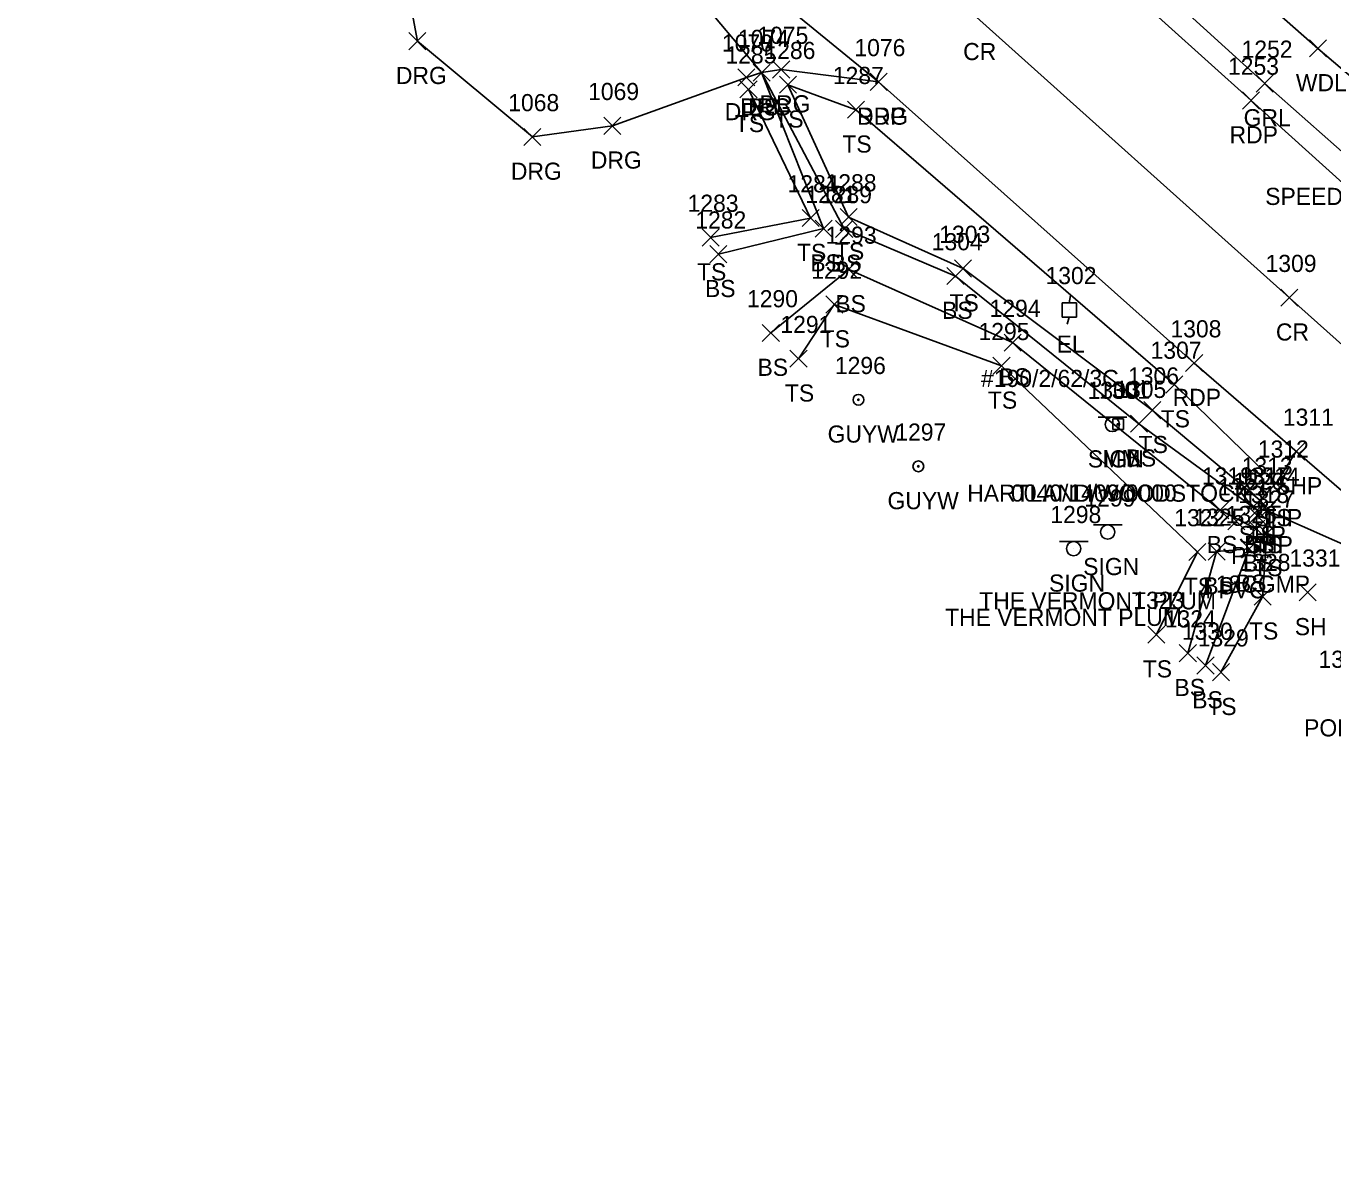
# Model space of a CAD drawing. Extents: x 1647133 to 1649138, y 411736 to 414924.
# Drawn here: x 1648782.9 to 1648935.4, y 411750.9 to 411884.6 of the extents above; entities that cross this region are included whole.
import ezdxf

# ---------------------------------------------------------------- set-up
doc = ezdxf.new("R2010")
doc.units = 0
for name, color, linetype in [('D_A', 7, 'Continuous'), ('D_C', 7, 'Continuous'), ('D_I', 7, 'Continuous'), ('D_TIC', 7, 'Continuous'), ('L_A', 7, 'Continuous'), ('L_I', 7, 'Continuous'), ('L_TIC', 7, 'Continuous'), ('LAWA', 7, 'Continuous'), ('LELB', 7, 'Continuous'), ('P_A', 7, 'Continuous'), ('P_I', 7, 'Continuous'), ('P_TIC', 7, 'Continuous'), ('PET', 7, 'Continuous'), ('PRC', 7, 'Continuous'), ('PSP', 7, 'Continuous'), ('R_A', 7, 'Continuous'), ('R_I', 7, 'Continuous'), ('R_TIC', 7, 'Continuous'), ('RDG', 7, 'Continuous'), ('RGR', 7, 'Continuous'), ('S_A', 7, 'Continuous'), ('S_C', 7, 'Continuous'), ('S_I', 7, 'Continuous'), ('SRM', 7, 'Continuous'), ('SSGN', 7, 'Continuous'), ('U_A', 7, 'Continuous'), ('U_C', 7, 'Continuous'), ('U_I', 7, 'Continuous'), ('UEPT', 7, 'Continuous'), ('UPGW', 7, 'Continuous')]:
    doc.layers.add(name, color=color, linetype=linetype)

msp = doc.modelspace()

# ---------------------------------------------------------------- linework, layer by layer
at = {"layer": 'D_TIC'}
for points in [[(1648923.17, 411825.82), (1648925.17, 411827.82)], [(1648925.17, 411825.82), (1648923.17, 411827.82)], [(1648925.57, 411826.48), (1648927.57, 411828.48)], [(1648927.57, 411826.48), (1648925.57, 411828.48)]]:
    msp.add_lwpolyline(points, dxfattribs=at)
at = {"layer": 'L_TIC'}
for points in [[(1648932.69, 411880.99), (1648934.69, 411882.99)], [(1648934.69, 411880.99), (1648932.69, 411882.99)], [(1648867.76, 411878.16), (1648869.76, 411880.16)], [(1648869.76, 411878.16), (1648867.76, 411880.16)], [(1648867.76, 411878.16), (1648869.76, 411880.16)], [(1648869.76, 411878.16), (1648867.76, 411880.16)], [(1648866.23, 411876.22), (1648868.23, 411878.22)], [(1648868.23, 411876.22), (1648866.23, 411878.22)], [(1648870.83, 411876.75), (1648872.83, 411878.75)], [(1648872.83, 411876.75), (1648870.83, 411878.75)], [(1648870.83, 411876.75), (1648872.83, 411878.75)], [(1648872.83, 411876.75), (1648870.83, 411878.75)], [(1648878.77, 411873.83), (1648880.77, 411875.83)], [(1648880.77, 411873.83), (1648878.77, 411875.83)], [(1648873.48, 411861.19), (1648875.48, 411863.19)], [(1648875.48, 411861.19), (1648873.48, 411863.19)], [(1648877.91, 411861.31), (1648879.91, 411863.31)], [(1648879.91, 411861.31), (1648877.91, 411863.31)], [(1648861.81, 411858.92), (1648863.81, 411860.92)], [(1648863.81, 411858.92), (1648861.81, 411860.92)], [(1648875, 411859.96), (1648877, 411861.96)], [(1648877, 411859.96), (1648875, 411861.96)], [(1648877.39, 411859.92), (1648879.39, 411861.92)], [(1648879.39, 411859.92), (1648877.39, 411861.92)], [(1648862.71, 411856.97), (1648864.71, 411858.97)], [(1648864.71, 411856.97), (1648862.71, 411858.97)], [(1648877.92, 411855.2), (1648879.92, 411857.2)], [(1648879.92, 411855.2), (1648877.92, 411857.2)], [(1648890.38, 411854.43), (1648892.38, 411856.43)], [(1648892.38, 411854.43), (1648890.38, 411856.43)], [(1648891.27, 411855.3), (1648893.27, 411857.3)], [(1648893.27, 411855.3), (1648891.27, 411857.3)], [(1648876.24, 411851.1), (1648878.24, 411853.1)], [(1648878.24, 411851.1), (1648876.24, 411853.1)], [(1648868.83, 411847.78), (1648870.83, 411849.78)], [(1648870.83, 411847.78), (1648868.83, 411849.78)], [(1648897.05, 411846.66), (1648899.05, 411848.66)], [(1648899.05, 411846.66), (1648897.05, 411848.66)], [(1648872.07, 411844.78), (1648874.07, 411846.78)], [(1648874.07, 411844.78), (1648872.07, 411846.78)], [(1648895.76, 411843.95), (1648897.76, 411845.95)], [(1648897.76, 411843.95), (1648895.76, 411845.95)], [(1648915.93, 411841.77), (1648917.93, 411843.77)], [(1648917.93, 411841.77), (1648915.93, 411843.77)], [(1648913.35, 411838.77), (1648915.35, 411840.77)], [(1648915.35, 411838.77), (1648913.35, 411840.77)], [(1648911.8, 411837.2), (1648913.8, 411839.2)], [(1648913.8, 411837.2), (1648911.8, 411839.2)], [(1648927.8, 411830.24), (1648929.8, 411832.24)], [(1648929.8, 411830.24), (1648927.8, 411832.24)], [(1648925.91, 411828.26), (1648927.91, 411830.26)], [(1648927.91, 411828.26), (1648925.91, 411830.26)], [(1648921.27, 411827.1), (1648923.27, 411829.1)], [(1648923.27, 411827.1), (1648921.27, 411829.1)], [(1648921.27, 411827.1), (1648923.27, 411829.1)], [(1648923.27, 411827.1), (1648921.27, 411829.1)], [(1648925.61, 411827.1), (1648927.61, 411829.1)], [(1648927.61, 411827.1), (1648925.61, 411829.1)], [(1648926.73, 411827.08), (1648928.73, 411829.08)], [(1648928.73, 411827.08), (1648926.73, 411829.08)], [(1648925.49, 411824.94), (1648927.49, 411826.94)], [(1648927.49, 411824.94), (1648925.49, 411826.94)], [(1648926.72, 411824.41), (1648928.72, 411826.41)], [(1648928.72, 411824.41), (1648926.72, 411826.41)], [(1648918.61, 411822.23), (1648920.61, 411824.23)], [(1648920.61, 411822.23), (1648918.61, 411824.23)], [(1648920.86, 411822.28), (1648922.86, 411824.28)], [(1648922.86, 411822.28), (1648920.86, 411824.28)], [(1648924.67, 411822.59), (1648926.67, 411824.59)], [(1648926.67, 411822.59), (1648924.67, 411824.59)], [(1648931.49, 411817.52), (1648933.49, 411819.52)], [(1648933.49, 411817.52), (1648931.49, 411819.52)], [(1648926.23, 411817.01), (1648928.23, 411819.01)], [(1648928.23, 411817.01), (1648926.23, 411819.01)], [(1648913.83, 411812.59), (1648915.83, 411814.59)], [(1648915.83, 411812.59), (1648913.83, 411814.59)], [(1648917.5, 411810.42), (1648919.5, 411812.42)], [(1648919.5, 411810.42), (1648917.5, 411812.42)], [(1648919.57, 411808.98), (1648921.57, 411810.98)], [(1648921.57, 411808.98), (1648919.57, 411810.98)], [(1648921.36, 411808.2), (1648923.36, 411810.2)], [(1648923.36, 411808.2), (1648921.36, 411810.2)]]:
    msp.add_lwpolyline(points, dxfattribs=at)
at = {"layer": 'LAWA'}
msp.add_lwpolyline([(1648868.17, 411960.17), (1648864.04, 411954.98), (1648884.1, 411929.27), (1648898.93, 411912.58), (1648933.69, 411881.99), (1648961.81, 411858.05), (1648999.6, 411820.73), (1649038.84, 411784.04)], dxfattribs=at)
at = {"layer": 'LELB'}
for points in [[(1648751.1, 411983.83), (1648760.09, 411978.22), (1648771.97, 411970.92), (1648795.55, 411950.44), (1648830.26, 411918.42), (1648852.65, 411898.35), (1648868.76, 411879.16), (1648878.39, 411860.92), (1648891.38, 411855.43), (1648912.8, 411838.2), (1648926.61, 411828.1), (1648926.49, 411825.94), (1648922.27, 411828.1)], [(1648868.76, 411879.16), (1648876, 411860.96), (1648863.71, 411857.97)], [(1648871.83, 411877.75), (1648879.77, 411874.83), (1648916.93, 411842.77), (1648928.8, 411831.24)], [(1648871.83, 411877.75), (1648878.91, 411862.31), (1648892.27, 411856.3), (1648914.35, 411839.77), (1648926.91, 411829.26)], [(1648862.81, 411859.92), (1648874.48, 411862.19), (1648867.23, 411877.22)], [(1648869.83, 411848.78), (1648878.92, 411856.2), (1648898.05, 411847.66), (1648922.27, 411828.1)], [(1648873.07, 411845.78), (1648877.24, 411852.1), (1648896.76, 411844.95), (1648919.61, 411823.23), (1648914.83, 411813.59)], [(1648927.73, 411828.08), (1648927.72, 411825.41), (1648927.23, 411818.01), (1648922.36, 411809.2)], [(1648918.5, 411811.42), (1648921.86, 411823.28), (1648925.67, 411823.59), (1648920.57, 411809.98)]]:
    msp.add_lwpolyline(points, dxfattribs=at)
at = {"layer": 'P_TIC'}
for points in [[(1648881.41, 411877.08), (1648883.41, 411879.08)], [(1648883.41, 411877.08), (1648881.41, 411879.08)], [(1648924.88, 411874.91), (1648926.88, 411876.91)], [(1648926.88, 411874.91), (1648924.88, 411876.91)], [(1648929.35, 411851.9), (1648931.35, 411853.9)], [(1648931.35, 411851.9), (1648929.35, 411853.9)], [(1648918.24, 411844.27), (1648920.24, 411846.27)], [(1648920.24, 411844.27), (1648918.24, 411846.27)], [(1648930.15, 411833.96), (1648932.15, 411835.96)], [(1648932.15, 411833.96), (1648930.15, 411835.96)], [(1648927.8, 411830.24), (1648929.8, 411832.24)], [(1648929.8, 411830.24), (1648927.8, 411832.24)], [(1648925.91, 411828.26), (1648927.91, 411830.26)], [(1648927.91, 411828.26), (1648925.91, 411830.26)], [(1648926.73, 411827.08), (1648928.73, 411829.08)], [(1648928.73, 411827.08), (1648926.73, 411829.08)]]:
    msp.add_lwpolyline(points, dxfattribs=at)
at = {"layer": 'PET'}
for points in [[(1648755.32, 411988.12), (1648772.85, 411971.96), (1648796.64, 411951.34), (1648831.69, 411920.96), (1648865.67, 411891.79), (1648882.41, 411878.08), (1648919.24, 411845.27), (1648942.74, 411824.95), (1648978.24, 411792.71), (1649017.21, 411756.44)], [(1648794.52, 411987.62), (1648826.41, 411959.79), (1648844.85, 411943.99), (1648873.22, 411921.13), (1648895.79, 411903), (1648925.88, 411875.91), (1648954.39, 411850.18), (1648992.64, 411815.07), (1649033.55, 411777.71)]]:
    msp.add_lwpolyline(points, dxfattribs=at)
at = {"layer": 'PRC'}
msp.add_lwpolyline([(1648523.86, 412428.16), (1648541.76, 412388.82), (1648560.79, 412347.22), (1648578.95, 412307.66), (1648596.52, 412268.85), (1648615.51, 412228.06), (1648629.38, 412198.52), (1648645.41, 412164.54), (1648659.58, 412134.14), (1648672.04, 412110.75), (1648683.9, 412091.11), (1648700.38, 412068.34), (1648715.84, 412049.98), (1648739.6, 412024.91), (1648761.87, 412004.35), (1648787.64, 411981.06), (1648820.99, 411950.62), (1648837.38, 411936.25), (1648865.13, 411910.89), (1648893.84, 411885.62), (1648930.35, 411852.9), (1648951.42, 411834.1), (1648988.1, 411800.42), (1649025.04, 411766.66)], dxfattribs=at)
at = {"layer": 'PSP'}
msp.add_lwpolyline([(1648931.15, 411834.96), (1648928.8, 411831.24), (1648926.91, 411829.26), (1648927.73, 411828.08), (1648939.73, 411822.73), (1648964.42, 411800.01), (1648974.69, 411788.64), (1648992.31, 411775.04), (1649001.21, 411767.13), (1649011.98, 411750.9)], dxfattribs=at)
at = {"layer": 'R_TIC'}
for points in [[(1648827.59, 411881.83), (1648829.59, 411883.83)], [(1648829.59, 411881.83), (1648827.59, 411883.83)], [(1648870.04, 411878.52), (1648872.04, 411880.52)], [(1648872.04, 411878.52), (1648870.04, 411880.52)], [(1648865.98, 411877.61), (1648867.98, 411879.61)], [(1648867.98, 411877.61), (1648865.98, 411879.61)], [(1648867.76, 411878.16), (1648869.76, 411880.16)], [(1648869.76, 411878.16), (1648867.76, 411880.16)], [(1648881.41, 411877.08), (1648883.41, 411879.08)], [(1648883.41, 411877.08), (1648881.41, 411879.08)], [(1648926.47, 411876.9), (1648928.47, 411878.9)], [(1648928.47, 411876.9), (1648926.47, 411878.9)], [(1648850.34, 411871.96), (1648852.34, 411873.96)], [(1648852.34, 411871.96), (1648850.34, 411873.96)], [(1648841.01, 411870.66), (1648843.01, 411872.66)], [(1648843.01, 411870.66), (1648841.01, 411872.66)]]:
    msp.add_lwpolyline(points, dxfattribs=at)
at = {"layer": 'RDG'}
msp.add_lwpolyline([(1648748.72, 411946.39), (1648758.46, 411944.73), (1648791.74, 411919.09), (1648813.93, 411903.47), (1648826.57, 411893.62), (1648828.59, 411882.83), (1648842.01, 411871.66), (1648851.34, 411872.96), (1648866.98, 411878.61), (1648868.76, 411879.16), (1648871.04, 411879.52), (1648882.41, 411878.08)], dxfattribs=at)
at = {"layer": 'RGR'}
msp.add_lwpolyline([(1648880.49, 411926.76), (1648895.83, 411907.68), (1648906.01, 411897.4), (1648927.47, 411877.9), (1648955.92, 411852.75), (1648995.16, 411817.25), (1649035.9, 411780.09)], dxfattribs=at)
at = {"layer": 'SRM'}
for p, q in [((1648910.98, 411838.77), (1648909.73, 411838.77)), ((1648909.73, 411838.77), (1648909.73, 411837.52)), ((1648910.98, 411838.77), (1648909.73, 411838.77)), ((1648909.73, 411838.77), (1648909.73, 411837.52)), ((1648910.98, 411837.52), (1648910.98, 411838.77)), ((1648910.98, 411837.52), (1648910.98, 411838.77)), ((1648909.73, 411837.52), (1648910.98, 411837.52)), ((1648909.73, 411837.52), (1648910.98, 411837.52))]:
    msp.add_line(p, q, dxfattribs=at)
msp.add_circle((1648910.33, 411838.11), 0.0833, dxfattribs=at)
at = {"layer": 'SSGN'}
for p, q in [((1648908.04, 411838.95), (1648911.37, 411838.95)), ((1648909.69, 411838.11), (1648909.69, 411838.11)), ((1648907.5, 411826.38), (1648910.84, 411826.38)), ((1648909.15, 411825.55), (1648909.15, 411825.55)), ((1648903.52, 411824.46), (1648906.85, 411824.46)), ((1648905.17, 411823.62), (1648905.17, 411823.62))]:
    msp.add_line(p, q, dxfattribs=at)
for centre in [(1648909.69, 411838.11), (1648909.15, 411825.55), (1648905.17, 411823.62)]:
    msp.add_circle(centre, 0.833, dxfattribs=at)
at = {"layer": 'UEPT'}
for p, q in [((1648904.82, 411853.14), (1648904.66, 411852.31)), ((1648903.82, 411850.64), (1648903.82, 411852.31)), ((1648903.82, 411852.31), (1648905.49, 411852.31)), ((1648904.66, 411851.48), (1648904.66, 411851.48)), ((1648905.49, 411852.31), (1648905.49, 411850.64)), ((1648905.49, 411850.64), (1648903.82, 411850.64)), ((1648904.41, 411849.81), (1648904.66, 411850.64))]:
    msp.add_line(p, q, dxfattribs=at)
at = {"layer": 'UPGW'}
for centre, radius in [((1648880.06, 411840.99), 0.625), ((1648880.06, 411840.99), 0.0833), ((1648887.05, 411833.22), 0.625), ((1648887.05, 411833.22), 0.0833)]:
    msp.add_circle(centre, radius, dxfattribs=at)

# ---------------------------------------------------------------- texts
at = {"layer": 'D_A'}
for p in [(1648925.95, 411822.48), (1648923.55, 411821.82)]:
    msp.add_text('P', height=2, dxfattribs=at).set_placement(p)
at = {"layer": 'D_C'}
for s, p in [('4 PVC', (1648919.83, 411817.82)), ('18CGMP', (1648921.76, 411818.48))]:
    msp.add_text(s, height=2, dxfattribs=at).set_placement(p)
at = {"layer": 'D_I'}
for s, p in [('1321', (1648922.04, 411829.82)), ('1320', (1648923.79, 411830.48))]:
    msp.add_text(s, height=2, dxfattribs=at).set_placement(p)
at = {"layer": 'L_A'}
for s, p in [('WDL', (1648931.11, 411876.99)), ('BS', (1648867.2, 411874.16)), ('BS', (1648867.2, 411874.16)), ('TS', (1648870.24, 411872.75)), ('TS', (1648870.24, 411872.75)), ('TS', (1648865.64, 411872.22)), ('TS', (1648878.18, 411869.83)), ('TS', (1648872.89, 411857.19)), ('TS', (1648877.32, 411857.31)), ('BS', (1648874.44, 411855.96)), ('BS', (1648876.83, 411855.92)), ('TS', (1648861.22, 411854.92)), ('BS', (1648862.15, 411852.97)), ('BS', (1648877.36, 411851.2)), ('TS', (1648890.68, 411851.3)), ('BS', (1648889.82, 411850.43)), ('TS', (1648875.65, 411847.1)), ('BS', (1648868.28, 411843.78)), ('BS', (1648896.49, 411842.66)), ('TS', (1648871.48, 411840.78)), ('TS', (1648895.17, 411839.95)), ('TS', (1648915.33, 411837.77)), ('TS', (1648912.76, 411834.77)), ('BS', (1648911.24, 411833.2)), ('TS', (1648927.21, 411826.24)), ('TS', (1648925.32, 411824.26)), ('BS', (1648920.71, 411823.1)), ('BS', (1648920.71, 411823.1)), ('BS', (1648925.05, 411823.1)), ('TS', (1648926.14, 411823.08)), ('BS', (1648924.93, 411820.94)), ('TS', (1648926.13, 411820.41)), ('TS', (1648918.02, 411818.23)), ('BS', (1648920.3, 411818.28)), ('BS', (1648924.11, 411818.59)), ('TS', (1648925.64, 411813.01)), ('SH', (1648930.98, 411813.52)), ('TS', (1648913.24, 411808.59)), ('BS', (1648916.94, 411806.42)), ('BS', (1648919.02, 411804.98)), ('TS', (1648920.77, 411804.2)), ('PORCH', (1648932.07, 411801.71))]:
    msp.add_text(s, height=2, dxfattribs=at).set_placement(p)
at = {"layer": 'L_I'}
for s, p in [('1074', (1648865.99, 411882.16)), ('1074', (1648865.99, 411882.16)), ('1285', (1648864.54, 411880.22)), ('1286', (1648869.09, 411880.75)), ('1286', (1648869.09, 411880.75)), ('1287', (1648877.07, 411877.83)), ('1284', (1648871.79, 411865.19)), ('1288', (1648876.22, 411865.31)), ('1281', (1648873.87, 411863.96)), ('1289', (1648875.69, 411863.92)), ('1283', (1648860.12, 411862.92)), ('1282', (1648861.02, 411860.97)), ('1293', (1648876.23, 411859.2)), ('1303', (1648889.49, 411859.3)), ('1304', (1648888.61, 411858.43)), ('1292', (1648874.55, 411855.1)), ('1290', (1648867.05, 411851.78)), ('1294', (1648895.36, 411850.66)), ('1291', (1648870.95, 411848.78)), ('1295', (1648894.07, 411847.95)), ('1307', (1648914.15, 411845.77)), ('1306', (1648911.52, 411842.77)), ('1305', (1648910.03, 411841.2)), ('1312', (1648926.67, 411834.24)), ('1319', (1648920.14, 411831.1)), ('1319', (1648920.14, 411831.1)), ('1317', (1648924.48, 411831.1)), ('1313', (1648924.78, 411832.26)), ('1314', (1648925.6, 411831.08)), ('1318', (1648924.37, 411828.94)), ('1327', (1648925.02, 411828.41)), ('1326', (1648922.92, 411826.59)), ('1322', (1648916.92, 411826.23)), ('1325', (1648919.16, 411826.28)), ('1328', (1648924.53, 411821.01)), ('1331', (1648930.36, 411821.52)), ('1323', (1648912.14, 411816.59)), ('1324', (1648915.81, 411814.42)), ('1330', (1648917.8, 411812.98)), ('1329', (1648919.66, 411812.2)), ('1332', (1648933.75, 411809.71))]:
    msp.add_text(s, height=2, dxfattribs=at).set_placement(p)
at = {"layer": 'P_A'}
for s, p in [('CR', (1648892.28, 411880.62)), ('RDP', (1648879.9, 411873.08)), ('RDP', (1648923.37, 411870.91)), ('CR', (1648928.78, 411847.9)), ('RDP', (1648916.73, 411840.27)), ('SHP', (1648928.68, 411829.96)), ('SHP', (1648926.34, 411826.24)), ('SHP', (1648924.44, 411824.26)), ('SHP', (1648925.26, 411823.08))]:
    msp.add_text(s, height=2, dxfattribs=at).set_placement(p)
at = {"layer": 'P_I'}
for s, p in [('1076', (1648879.59, 411881.08)), ('1253', (1648923.19, 411878.91)), ('1309', (1648927.57, 411855.9)), ('1308', (1648916.47, 411848.27)), ('1311', (1648929.59, 411837.96)), ('1312', (1648926.67, 411834.24)), ('1313', (1648924.78, 411832.26)), ('1314', (1648925.6, 411831.08))]:
    msp.add_text(s, height=2, dxfattribs=at).set_placement(p)
at = {"layer": 'R_A'}
for s, p in [('DRG', (1648826.08, 411877.83)), ('DRG', (1648866.25, 411874.16)), ('DRG', (1648868.52, 411874.52)), ('DRG', (1648864.46, 411873.61)), ('DRG', (1648879.9, 411873.08)), ('GRL', (1648925.01, 411872.9)), ('DRG', (1648848.83, 411867.96)), ('DRG', (1648839.5, 411866.66))]:
    msp.add_text(s, height=2, dxfattribs=at).set_placement(p)
at = {"layer": 'R_I'}
for s, p in [('1070', (1648864.12, 411881.61)), ('1074', (1648865.99, 411882.16)), ('1075', (1648868.26, 411882.52)), ('1076', (1648879.59, 411881.08)), ('1252', (1648924.77, 411880.9)), ('1069', (1648848.51, 411875.96)), ('1068', (1648839.19, 411874.66))]:
    msp.add_text(s, height=2, dxfattribs=at).set_placement(p)
at = {"layer": 'S_A'}
for s, p in [('SIGN', (1648906.83, 411833.09)), ('MM', (1648908.52, 411833.11)), ('SIGN', (1648906.29, 411820.53)), ('SIGN', (1648902.3, 411818.6))]:
    msp.add_text(s, height=2, dxfattribs=at).set_placement(p)
at = {"layer": 'S_C'}
for s, p in [('SPEED LIMIT 35', (1648927.53, 411863.72)), ('HARTLAND/WOODSTOCK', (1648892.75, 411829.09)), ('0040/1409/0000', (1648897.87, 411829.11)), ('THE VERMONT PLUM', (1648894.15, 411816.53)), ('THE VERMONT PLUM', (1648890.17, 411814.6))]:
    msp.add_text(s, height=2, dxfattribs=at).set_placement(p)
at = {"layer": 'S_I'}
for s, p in [('1300', (1648906.81, 411841.09)), ('1301', (1648908.13, 411841.11)), ('1299', (1648906.43, 411828.53)), ('1298', (1648902.45, 411826.6))]:
    msp.add_text(s, height=2, dxfattribs=at).set_placement(p)
at = {"layer": 'U_A'}
for s, p in [('EL', (1648903.19, 411846.48)), ('GUYW', (1648876.46, 411835.99)), ('GUYW', (1648883.45, 411828.22))]:
    msp.add_text(s, height=2, dxfattribs=at).set_placement(p)
at = {"layer": 'U_C'}
msp.add_text('#190/2/62/3C', height=2, dxfattribs=at).set_placement((1648894.37, 411842.48))
at = {"layer": 'U_I'}
for s, p in [('1302', (1648901.89, 411854.48)), ('1296', (1648877.31, 411843.99)), ('1297', (1648884.36, 411836.22))]:
    msp.add_text(s, height=2, dxfattribs=at).set_placement(p)

doc.saveas('drawing.dxf')
